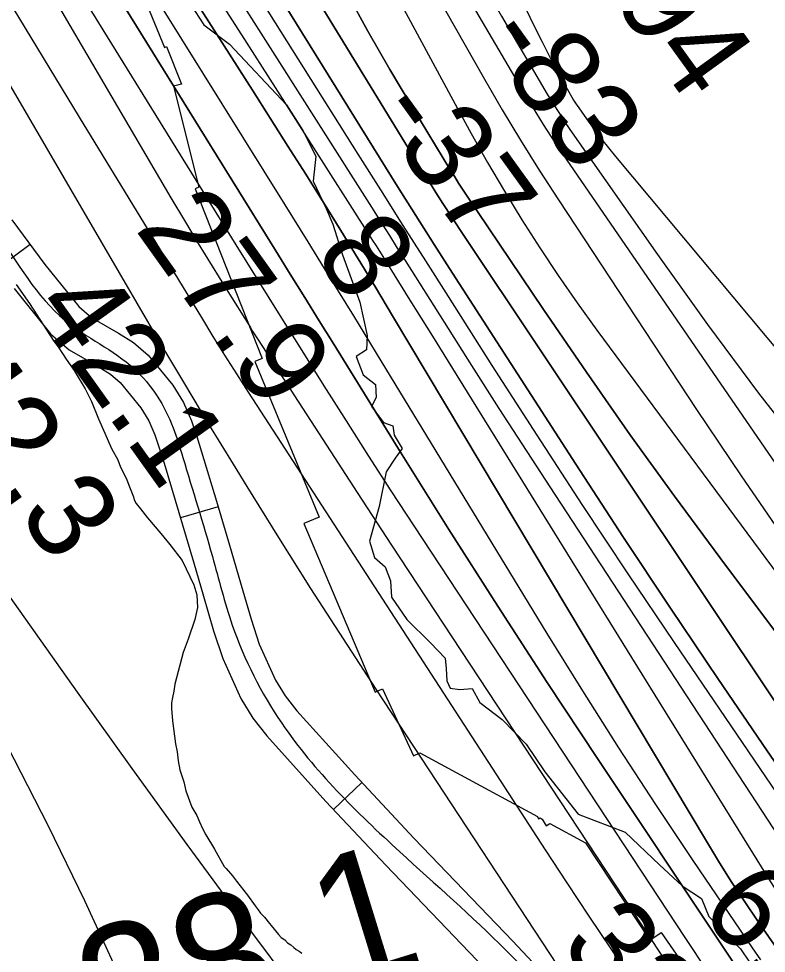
# Model space of a CAD drawing. Extents: x 3187622 to 3225504, y 800805 to 826213.
# Drawn here: x 3198341 to 3198914, y 817453 to 818168 of the extents above; entities that cross this region are included whole.
import ezdxf

# ---------------------------------------------------------------- set-up
doc = ezdxf.new("R2010")
doc.units = 0
for name, color, linetype in [('V-RIVR-EDGE', 7, 'Continuous'), ('V-RIVR-RANG', 7, 'Continuous'), ('V-ROAD-CNTR', 7, 'Continuous'), ('V-RRAP-RVMT', 7, 'Continuous'), ('V-SITE-VEGE', 7, 'Continuous'), ('V-SURV-IDEN', 7, 'Continuous'), ('V-TOPO-DPTH', 7, 'Continuous'), ('V-TOPO-MAJR', 7, 'Continuous'), ('V-TOPO-MINR', 7, 'Continuous'), ('V-TOPO-WATR', 7, 'Continuous')]:
    doc.layers.add(name, color=color, linetype=linetype)

msp = doc.modelspace()

# ---------------------------------------------------------------- linework, layer by layer
at = {"layer": 'V-RIVR-EDGE'}
msp.add_lwpolyline([(3198462.96, 818194.58), (3198482.88, 818163.67), (3198502.41, 818148.84), (3198546.19, 818102.22), (3198558.75, 818082.63), (3198568.7, 818063.05), (3198566.48, 818043.93), (3198576.43, 818023.04), (3198581.61, 818010.85), (3198588.94, 817987.36), (3198602.33, 817951.25), (3198607.92, 817925.59), (3198607.46, 817914.72), (3198599.62, 817909.53), (3198604.8, 817895.61), (3198614.35, 817888.19), (3198614.76, 817878.19), (3198611.26, 817871.25), (3198620.36, 817859.05), (3198627.74, 817856.43), (3198628.59, 817849.47), (3198634.65, 817839.02), (3198629.42, 817831.65), (3198622.44, 817821.23), (3198617.16, 817794.73), (3198609.7, 817768.23), (3198613.58, 817755.62), (3198621.82, 817748.64), (3198625.71, 817737.77), (3198626.55, 817725.16), (3198638.24, 817708.18), (3198656.45, 817690.31), (3198667.73, 817678.54), (3198668.58, 817670.72), (3198668.99, 817661.15), (3198671.58, 817655.5), (3198678.97, 817654.61), (3198688.53, 817655.46), (3198694.16, 817644.57), (3198711.51, 817631.49), (3198729.72, 817612.75), (3198744.01, 817591.42), (3198769.58, 817559.19), (3198805.63, 817545.19), (3198832.08, 817520.35), (3198849.43, 817504.22), (3198864.18, 817494.62), (3198869.8, 817480.7), (3198894.08, 817455.86), (3198901.01, 817445.85)], dxfattribs=at)
at = {"layer": 'V-ROAD-CNTR'}
for p, q in [((3198349.62, 817995.47), (3198325.52, 817977.61)), ((3198493.66, 817794.53), (3198464.91, 817785.96)), ((3198603.98, 817583.25), (3198582.07, 817562.75))]:
    msp.add_line(p, q, dxfattribs=at)
for points in [[(3198335.71, 818014.25), (3198361.06, 817980.02), (3198387.04, 817947.98), (3198397.07, 817939.27), (3198417.36, 817927.58), (3198429, 817920.3), (3198440.14, 817910.71), (3198459.12, 817887.67), (3198467.28, 817874.28), (3198473.37, 817860.33), (3198477.43, 817848.28), (3198481.06, 817836.69), (3198492.42, 817798.7), (3198503.73, 817760.74), (3198511.39, 817734.39), (3198518.94, 817708.35), (3198525.28, 817689.25), (3198537.72, 817661.79), (3198545.14, 817649.77), (3198554.02, 817638.31), (3198598.47, 817589.15), (3198643.9, 817540.57), (3198719.63, 817461.94), (3198795.23, 817381.27)], [(3198337.34, 817961.64), (3198365.39, 817927.05), (3198379.59, 817914.72), (3198401.92, 817901.86), (3198411.16, 817896.07), (3198418.62, 817889.65), (3198434.62, 817870.24), (3198440.6, 817860.41), (3198445.36, 817849.52), (3198448.9, 817839.01), (3198452.37, 817827.91), (3198463.67, 817790.12), (3198474.95, 817752.27), (3198482.58, 817726.03), (3198490.29, 817699.45), (3198497.3, 817678.3), (3198511.19, 817647.66), (3198520.45, 817632.65), (3198531.01, 817619.03), (3198576.38, 817568.84), (3198622.14, 817519.92), (3198697.88, 817441.28)]]:
    msp.add_lwpolyline(points, dxfattribs=at)
msp.add_spline([(3197108.01, 817982.2), (3197162.34, 817991.13), (3197229.38, 818001.88), (3197259.08, 817993.64), (3197361.14, 818001.17), (3197493.79, 818058.56), (3197592.21, 818133.8), (3197727.97, 818194.32), (3197773.22, 818262.2), (3197795.85, 818360.06), (3197841.1, 818435.29), (3197893.71, 818488.46), (3197938.96, 818518.44), (3197968.94, 818533.71), (3198014.19, 818525.8), (3198044.74, 818495.82), (3198127.32, 818420.58), (3198203.12, 818307.45), (3198233.1, 818209.03), (3198255.73, 818133.8), (3198278.35, 818073.27), (3198323.61, 818005.39), (3198376.21, 817937.52), (3198429.38, 817900.18), (3198459.36, 817854.93), (3198466.72, 817832.3), (3198489.34, 817756.51), (3198504.61, 817703.9), (3198542.51, 817628.67), (3198633.02, 817530.24), (3198783.48, 817371.86), (3198859.28, 817221.4), (3198934.51, 817108.26)], degree=3, dxfattribs=at)
at = {"layer": 'V-RRAP-RVMT'}
for p, q in [((3198437.21, 818183.77), (3198452.62, 818146.32)), ((3198452.62, 818146.32), (3198454.19, 818146.91)), ((3198454.19, 818146.91), (3198465.79, 818118.21)), ((3198465.79, 818118.21), (3198459.46, 818116.68)), ((3198459.46, 818116.68), (3198479.05, 818039.2)), ((3198479.05, 818039.2), (3198476.17, 818038.11)), ((3198476.17, 818038.11), (3198527.37, 817908.12)), ((3198527.37, 817908.12), (3198521.83, 817905.82)), ((3198521.83, 817905.82), (3198571.13, 817786.62)), ((3198571.13, 817786.62), (3198559.38, 817781.75)), ((3198559.38, 817781.75), (3198614.13, 817652.53)), ((3198614.13, 817652.53), (3198619.8, 817654.96)), ((3198619.8, 817654.96), (3198643.49, 817603.67)), ((3198643.49, 817603.67), (3198648.37, 817606.06)), ((3198648.37, 817606.06), (3198738.42, 817557.21)), ((3198738.42, 817557.21), (3198739.13, 817555.62)), ((3198739.13, 817555.62), (3198740.4, 817556.17)), ((3198740.4, 817556.17), (3198742.03, 817555.29)), ((3198742.03, 817555.29), (3198745.19, 817550.29)), ((3198745.19, 817550.29), (3198747.97, 817552.07)), ((3198747.97, 817552.07), (3198775.21, 817537.26)), ((3198775.21, 817537.26), (3198824.67, 817462.67)), ((3198824.67, 817462.67), (3198833.25, 817468.42)), ((3198833.25, 817468.42), (3198856.19, 817435.63))]:
    msp.add_line(p, q, dxfattribs=at)
at = {"layer": 'V-SITE-VEGE'}
for p, q in [((3198338.85, 817964.69), (3198349.09, 817950.23)), ((3198349.09, 817950.23), (3198367.96, 817921.3)), ((3198367.96, 817921.3), (3198371.23, 817916.89)), ((3198371.23, 817916.89), (3198377.39, 817907.65)), ((3198377.39, 817907.65), (3198383.53, 817898.82)), ((3198383.53, 817898.82), (3198391.75, 817884.74)), ((3198391.75, 817884.74), (3198396.69, 817875.08)), ((3198396.69, 817875.08), (3198402.07, 817861.8)), ((3198402.07, 817861.8), (3198407.03, 817850.93)), ((3198407.03, 817850.93), (3198411.99, 817839.25)), ((3198411.99, 817839.25), (3198416.93, 817830.4)), ((3198416.93, 817830.4), (3198419, 817824.76)), ((3198419, 817824.76), (3198423.53, 817815.91)), ((3198423.53, 817815.91), (3198425.19, 817811.08)), ((3198425.19, 817811.08), (3198428.92, 817802.22)), ((3198428.92, 817802.22), (3198429.34, 817799.8)), ((3198429.34, 817799.8), (3198430.99, 817796.98)), ((3198430.99, 817796.98), (3198434.26, 817792.97)), ((3198434.26, 817792.97), (3198439.58, 817786.15)), ((3198439.58, 817786.15), (3198449.8, 817774.12)), ((3198449.8, 817774.12), (3198456.75, 817765.69)), ((3198456.75, 817765.69), (3198466.17, 817753.25)), ((3198466.17, 817753.25), (3198475.23, 817734.74)), ((3198475.23, 817734.74), (3198477.33, 817727.08)), ((3198477.33, 817727.08), (3198477.82, 817717.38)), ((3198477.82, 817717.38), (3198475.89, 817708.07)), ((3198475.89, 817708.07), (3198470.78, 817693.06)), ((3198470.78, 817693.06), (3198466.83, 817682.92)), ((3198466.83, 817682.92), (3198460.59, 817658.6)), ((3198459.83, 817653.34), (3198458.67, 817648.48)), ((3198460.59, 817658.6), (3198459.83, 817653.34)), ((3198458.67, 817648.48), (3198457.9, 817644.43)), ((3198457.9, 817644.43), (3198457.94, 817639.98)), ((3198457.94, 817639.98), (3198458.83, 817630.69)), ((3198458.83, 817630.69), (3198461.02, 817612.92)), ((3198461.02, 817612.92), (3198462.29, 817606.87)), ((3198462.29, 817606.87), (3198463.17, 817600.01)), ((3198463.17, 817600.01), (3198464.44, 817593.15)), ((3198464.44, 817593.15), (3198467.36, 817583.88)), ((3198467.36, 817583.88), (3198469.04, 817577.02)), ((3198469.04, 817577.02), (3198473.61, 817564.53)), ((3198473.61, 817564.53), (3198477.31, 817558.1)), ((3198477.31, 817558.1), (3198479.38, 817553.27)), ((3198479.38, 817553.27), (3198481.85, 817548.04)), ((3198481.85, 817548.04), (3198484.32, 817543.21)), ((3198484.32, 817543.21), (3198490.89, 817532.36)), ((3198490.89, 817532.36), (3198498.29, 817519.08)), ((3198498.29, 817519.08), (3198499.93, 817517.48)), ((3198499.93, 817517.48), (3198504.83, 817511.87)), ((3198504.83, 817511.87), (3198507.7, 817507.86)), ((3198507.7, 817507.86), (3198516.29, 817497.02)), ((3198516.29, 817497.02), (3198522.02, 817488.99)), ((3198522.02, 817488.99), (3198524.48, 817485.78)), ((3198524.48, 817485.78), (3198526.12, 817483.37)), ((3198526.12, 817483.37), (3198529.39, 817480.17)), ((3198529.39, 817480.17), (3198533.07, 817475.35)), ((3198533.07, 817475.35), (3198534.3, 817473.74)), ((3198534.3, 817473.74), (3198540.02, 817466.93)), ((3198540.02, 817466.93), (3198542.06, 817464.52)), ((3198542.06, 817464.52), (3198544.91, 817462.93)), ((3198544.91, 817462.93), (3198546.95, 817460.52)), ((3198546.95, 817460.52), (3198549.39, 817458.93)), ((3198549.39, 817458.93), (3198551.84, 817456.93)), ((3198551.84, 817456.93), (3198553.47, 817455.33)), ((3198553.47, 817455.33), (3198555.91, 817454.14)), ((3198555.91, 817454.14), (3198557.95, 817452.54))]:
    msp.add_line(p, q, dxfattribs=at)
at = {"layer": 'V-TOPO-DPTH'}
for points in [[(3198152.22, 818754.17), (3198256.7, 818585.99), (3198313.23, 818495.3), (3198369.94, 818404.72), (3198426.92, 818314.32), (3198484.09, 818224.03), (3198612.93, 818021.23), (3198618.97, 818011.71), (3198625, 818002.2), (3198631.02, 817992.67), (3198637.03, 817983.15), (3198666.84, 817935.85), (3198687.84, 817902.72), (3198708.96, 817869.67), (3198730.25, 817836.73), (3198751.65, 817803.86), (3198932.33, 817527.96), (3198948.71, 817503.46), (3198965.4, 817479.17), (3198982.55, 817455.21), (3199000.01, 817431.46)], [(3198152.22, 818754.17), (3198256.7, 818585.99), (3198313.23, 818495.3), (3198369.94, 818404.72), (3198426.92, 818314.32), (3198484.09, 818224.03), (3198612.93, 818021.23), (3198618.97, 818011.71), (3198625, 818002.2), (3198631.02, 817992.67), (3198637.03, 817983.15), (3198666.84, 817935.85), (3198687.84, 817902.72), (3198708.96, 817869.67), (3198730.25, 817836.73), (3198751.65, 817803.86), (3198932.33, 817527.96), (3198948.71, 817503.46), (3198965.4, 817479.17), (3198982.55, 817455.21), (3199000.01, 817431.46)], [(3198987.7, 817544.61), (3198679.53, 818006.19), (3198671.32, 818018.65), (3198663.2, 818031.18), (3198655.24, 818043.8), (3198647.38, 818056.48), (3198566.36, 818188.91), (3198518.5, 818268.12), (3198471.22, 818347.66), (3198424.8, 818427.72), (3198378.97, 818508.11), (3198244.61, 818746.78)], [(3198244.61, 818746.78), (3198378.97, 818508.11), (3198424.8, 818427.72), (3198471.22, 818347.66), (3198518.5, 818268.12), (3198566.36, 818188.91), (3198647.38, 818056.48), (3198655.24, 818043.8), (3198663.2, 818031.18), (3198671.32, 818018.65), (3198679.53, 818006.19), (3198987.7, 817544.61)], [(3198925.67, 817450.87), (3198923.65, 817453.73), (3198907.29, 817477.27), (3198897.26, 817492.01), (3198887.44, 817506.88), (3198877.94, 817521.95), (3198868.64, 817537.16), (3198627.43, 817940.81), (3198614.32, 817962.59), (3198601.12, 817984.33), (3198587.78, 818005.98), (3198574.36, 818027.57), (3198560.84, 818049.11), (3198547.28, 818070.62), (3198533.65, 818092.09), (3198519.99, 818113.54), (3198140.09, 818707.79)], [(3198140.09, 818707.79), (3198519.99, 818113.54), (3198533.65, 818092.09), (3198547.28, 818070.62), (3198560.84, 818049.11), (3198574.36, 818027.57), (3198587.78, 818005.98), (3198601.12, 817984.33), (3198614.32, 817962.59), (3198627.43, 817940.81), (3198868.64, 817537.16), (3198877.94, 817521.95), (3198887.44, 817506.88), (3198897.26, 817492.01), (3198907.29, 817477.27), (3198923.65, 817453.73), (3198925.67, 817450.87)], [(3199249.34, 817166.94), (3199005.9, 817477.94), (3198997.72, 817488.6), (3198989.66, 817499.34), (3198981.8, 817510.23), (3198974.07, 817521.22), (3198914.39, 817607.66), (3198877.17, 817662.11), (3198840.29, 817716.78), (3198803.92, 817771.8), (3198767.9, 817827.05), (3198673.42, 817973.41), (3198659.28, 817995.44), (3198645.22, 818017.52), (3198631.27, 818039.68), (3198617.4, 818061.88), (3198320.09, 818540.42), (3198295.32, 818580.49), (3198270.68, 818620.65), (3198246.22, 818660.91), (3198221.89, 818701.26)], [(3198221.89, 818701.26), (3198246.22, 818660.91), (3198270.68, 818620.65), (3198295.32, 818580.49), (3198320.09, 818540.42), (3198617.4, 818061.88), (3198631.27, 818039.68), (3198645.22, 818017.52), (3198659.28, 817995.44), (3198673.42, 817973.41), (3198767.9, 817827.05), (3198803.92, 817771.8), (3198840.29, 817716.78), (3198877.17, 817662.11), (3198914.39, 817607.66), (3198974.07, 817521.22), (3198981.8, 817510.23), (3198989.66, 817499.34), (3198997.72, 817488.6), (3199005.9, 817477.94), (3199249.34, 817166.94)], [(3198890.07, 817443.38), (3198878.59, 817460.42), (3198784.36, 817601.69), (3198745.96, 817659.89), (3198707.96, 817718.35), (3198670.55, 817777.18), (3198633.53, 817836.27), (3198582.29, 817918.99), (3198571.19, 817936.91), (3198560.09, 817954.82), (3198548.98, 817972.73), (3198537.86, 817990.64), (3198175.24, 818574.89), (3198158.91, 818601.16), (3198142.54, 818627.4), (3198126.13, 818653.62), (3198109.68, 818679.82)], [(3199002.45, 817590.04), (3198878.11, 817755.74), (3198843.49, 817802.62), (3198809.35, 817849.85), (3198775.95, 817897.59), (3198743.03, 817945.68), (3198684.1, 818033.21), (3198681.04, 818037.81), (3198678.02, 818042.45), (3198675.07, 818047.12), (3198672.16, 818051.82), (3198642.62, 818100.22), (3198625.31, 818129.33), (3198608.45, 818158.7), (3198592.29, 818188.44), (3198576.57, 818218.45), (3198536.12, 818297.92), (3198500.47, 818367.83), (3198464.76, 818437.7), (3198428.95, 818507.52), (3198393.07, 818577.31), (3198346.96, 818666.85)], [(3198346.96, 818666.85), (3198393.07, 818577.31), (3198428.95, 818507.52), (3198464.76, 818437.7), (3198500.47, 818367.83), (3198536.12, 818297.92), (3198576.57, 818218.45), (3198592.29, 818188.44), (3198608.45, 818158.7), (3198625.31, 818129.33), (3198642.62, 818100.22), (3198672.16, 818051.82), (3198675.07, 818047.12), (3198678.02, 818042.45), (3198681.04, 818037.81), (3198684.1, 818033.21), (3198743.03, 817945.68), (3198775.95, 817897.59), (3198809.35, 817849.85), (3198843.49, 817802.62), (3198878.11, 817755.74), (3199002.45, 817590.04)]]:
    msp.add_lwpolyline(points, dxfattribs=at)
at = {"layer": 'V-TOPO-MAJR'}
for points in [[(3198342.95, 818716.99), (3198374.42, 818659.39), (3198405.82, 818601.75), (3198437.12, 818544.05), (3198468.34, 818486.32), (3198675.34, 818102.78), (3198687.67, 818080.41), (3198700.27, 818058.2), (3198713.26, 818036.21), (3198726.51, 818014.37), (3198740.23, 817992.83), (3198754.3, 817971.53), (3198768.89, 817950.58), (3198783.84, 817929.87), (3199038.64, 817585.91), (3199049.32, 817571.77), (3199060.18, 817557.77), (3199071.3, 817543.98), (3199082.59, 817530.32), (3199213.51, 817375.02), (3199266.5, 817312.77), (3199319.89, 817250.88), (3199373.89, 817189.52)], [(3198051.2, 818669.08), (3198170.24, 818460.43), (3198223.54, 818367.96), (3198277.39, 818275.8), (3198332.05, 818184.13), (3198387.25, 818092.77), (3198480.89, 817939.34), (3198489.73, 817924.98), (3198498.66, 817910.67), (3198507.71, 817896.43), (3198516.84, 817882.25), (3198744.39, 817531.87), (3198761.04, 817506.43), (3198777.81, 817481.08), (3198794.77, 817455.84), (3198811.85, 817430.69)]]:
    msp.add_lwpolyline(points, dxfattribs=at)
at = {"layer": 'V-TOPO-MINR'}
for points in [[(3198322.86, 818793.33), (3198394.83, 818662), (3198443.95, 818572.84), (3198493.33, 818483.83), (3198543.13, 818395.04), (3198593.19, 818306.4), (3198697.9, 818121.96), (3198711.51, 818098.54), (3198725.43, 818075.3), (3198739.8, 818052.35), (3198754.48, 818029.58), (3198860.3, 817869.04), (3198894.51, 817818.1), (3198929.31, 817767.57), (3198964.97, 817717.65), (3199001.22, 817668.13), (3199064.91, 817582.69), (3199069.8, 817576.25), (3199074.78, 817569.88), (3199079.87, 817563.6), (3199085.05, 817557.38), (3199131.67, 817502.48), (3199160.38, 817469.02), (3199189.33, 817435.75)], [(3198349.13, 818785.06), (3198502.32, 818505.68), (3198541.3, 818435.29), (3198580.69, 818365.14), (3198620.67, 818295.32), (3198661.05, 818225.73), (3198725.88, 818115.13), (3198734.3, 818101.11), (3198742.92, 818087.21), (3198751.85, 818073.51), (3198760.97, 818059.94), (3199041.41, 817652.3), (3199049.56, 817640.74), (3199057.88, 817629.32), (3199066.46, 817618.09), (3199075.22, 817606.98), (3199084.24, 817596.09), (3199093.43, 817585.36), (3199102.89, 817574.85), (3199112.52, 817564.5), (3199476.76, 817182.58)], [(3198152.22, 818754.17), (3198256.7, 818585.99), (3198313.23, 818495.3), (3198369.94, 818404.72), (3198426.92, 818314.32), (3198484.09, 818224.03), (3198612.93, 818021.23), (3198618.97, 818011.71), (3198625, 818002.2), (3198631.02, 817992.67), (3198637.03, 817983.15), (3198666.84, 817935.85), (3198687.84, 817902.72), (3198708.96, 817869.67), (3198730.25, 817836.73), (3198751.65, 817803.86), (3198932.33, 817527.96), (3198948.71, 817503.46), (3198965.4, 817479.17), (3198982.55, 817455.21), (3199000.01, 817431.46)], [(3198244.61, 818746.78), (3198378.97, 818508.11), (3198424.8, 818427.72), (3198471.22, 818347.66), (3198518.5, 818268.12), (3198566.36, 818188.91), (3198647.38, 818056.48), (3198655.24, 818043.8), (3198663.2, 818031.18), (3198671.32, 818018.65), (3198679.53, 818006.19), (3198987.7, 817544.61)], [(3198146.49, 818732.38), (3198460.28, 818236.76), (3198485.93, 818196.31), (3198511.61, 818155.88), (3198537.36, 818115.49), (3198563.14, 818075.12), (3198609.55, 818002.54), (3198612.15, 817998.47), (3198614.73, 817994.4), (3198617.3, 817990.32), (3198619.86, 817986.23), (3198632.07, 817966.7), (3198640.72, 817952.83), (3198649.36, 817938.96), (3198657.99, 817925.08), (3198666.61, 817911.2), (3198913.25, 817513.32), (3198929.31, 817487.96), (3198945.7, 817462.82), (3198962.58, 817438)], [(3198466.98, 818733.21), (3198505.3, 818656.53), (3198542.98, 818579.54), (3198579.71, 818502.08), (3198615.8, 818424.32), (3198717.54, 818201.49), (3198723.5, 818188.64), (3198729.56, 818175.85), (3198735.78, 818163.13), (3198742.11, 818150.46), (3198749.32, 818136.22), (3198752.17, 818130.74), (3198755.08, 818125.29), (3198758.09, 818119.89), (3198761.16, 818114.53), (3198766.15, 818106.03), (3198768.15, 818102.86), (3198768.87, 818101.82), (3198777.35, 818089.86), (3198782.39, 818082.92), (3198787.55, 818076.07), (3198792.87, 818069.34), (3198798.3, 818062.69), (3199147.53, 817645.35)], [(3198066.75, 818719.59), (3198161.12, 818561.11), (3198210.21, 818479.12), (3198259.59, 818397.31), (3198309.38, 818315.74), (3198359.45, 818234.35), (3198507.41, 817995.17), (3198524.18, 817968.12), (3198540.98, 817941.09), (3198557.84, 817914.09), (3198574.73, 817887.11), (3198591.73, 817860.21), (3198608.86, 817833.38), (3198626.16, 817806.67), (3198643.59, 817780.03), (3198851.41, 817464.63), (3198868.53, 817438.89)], [(3198419.45, 818715.85), (3198626.69, 818321.97), (3198647.16, 818283.7), (3198667.98, 818245.63), (3198689.32, 818207.85), (3198711.01, 818170.26), (3198746.01, 818110.58), (3198750.55, 818103.04), (3198755.22, 818095.57), (3198760.06, 818088.22), (3198765.02, 818080.95), (3198830.36, 817987.6), (3198868.72, 817934.2), (3198907.92, 817881.44), (3198948.4, 817829.65), (3198989.73, 817778.51), (3199096.02, 817650.22), (3199111.57, 817631.74), (3199127.31, 817613.43), (3199143.34, 817595.36), (3199159.55, 817577.46), (3199252.09, 817476.87), (3199312.31, 817411.03), (3199372.27, 817344.96)], [(3198062.25, 818704.66), (3198457.57, 818031.14), (3198467.95, 818013.63), (3198478.42, 817996.18), (3198489.05, 817978.82), (3198499.77, 817961.52), (3198518.43, 817931.69), (3198519.9, 817929.35), (3198521.38, 817927.01), (3198522.88, 817924.68), (3198524.38, 817922.35), (3198573.97, 817846.01), (3198600.32, 817805.54), (3198626.71, 817765.1), (3198653.19, 817724.72), (3198679.72, 817684.37), (3198852.66, 817421.96)], [(3198221.89, 818701.26), (3198246.22, 818660.91), (3198270.68, 818620.65), (3198295.32, 818580.49), (3198320.09, 818540.42), (3198617.4, 818061.88), (3198631.27, 818039.68), (3198645.22, 818017.52), (3198659.28, 817995.44), (3198673.42, 817973.41), (3198767.9, 817827.05), (3198803.92, 817771.8), (3198840.29, 817716.78), (3198877.17, 817662.11), (3198914.39, 817607.66), (3198974.07, 817521.22), (3198981.8, 817510.23), (3198989.66, 817499.34), (3198997.72, 817488.6), (3199005.9, 817477.94), (3199249.34, 817166.94)], [(3198109.68, 818679.82), (3198126.13, 818653.62), (3198142.54, 818627.4), (3198158.91, 818601.16), (3198175.24, 818574.89), (3198537.86, 817990.64), (3198548.98, 817972.73), (3198560.09, 817954.82), (3198571.19, 817936.91), (3198582.29, 817918.99), (3198633.53, 817836.27), (3198670.55, 817777.18), (3198707.96, 817718.35), (3198745.96, 817659.89), (3198784.36, 817601.69), (3198878.59, 817460.42), (3198890.07, 817443.38)], [(3198132.86, 818681.23), (3198213.39, 818554.16), (3198272.67, 818460.38), (3198331.82, 818366.51), (3198390.76, 818272.52), (3198449.57, 818178.44), (3198544.75, 818025.8), (3198562.36, 817997.46), (3198579.91, 817969.08), (3198597.38, 817940.65), (3198614.79, 817912.18), (3198745.63, 817697.5), (3198772.87, 817653.55), (3198800.52, 817609.87), (3198828.82, 817566.6), (3198857.54, 817523.61), (3198902.94, 817456.73), (3198909.33, 817447.42)], [(3198214.61, 818677.59), (3198226.59, 818658.48), (3198600.84, 818064.65), (3198618.08, 818037.34), (3198635.34, 818010.04), (3198652.64, 817982.76), (3198669.96, 817955.5), (3198703.5, 817902.8), (3198737.84, 817849.36), (3198772.52, 817796.13), (3198807.68, 817743.23), (3198843.16, 817690.53), (3198956.53, 817523.83), (3198967.97, 817507.34), (3198979.61, 817491), (3198991.55, 817474.87), (3199003.69, 817458.89), (3199374.89, 816979.49)], [(3198346.96, 818666.85), (3198393.07, 818577.31), (3198428.95, 818507.52), (3198464.76, 818437.7), (3198500.47, 818367.83), (3198536.12, 818297.92), (3198576.57, 818218.45), (3198592.29, 818188.44), (3198608.45, 818158.7), (3198625.31, 818129.33), (3198642.62, 818100.22), (3198672.16, 818051.82), (3198675.07, 818047.12), (3198678.02, 818042.45), (3198681.04, 818037.81), (3198684.1, 818033.21), (3198743.03, 817945.68), (3198775.95, 817897.59), (3198809.35, 817849.85), (3198843.49, 817802.62), (3198878.11, 817755.74), (3199002.45, 817590.04)], [(3198020.05, 818661.79), (3198038.46, 818628.67), (3198052.11, 818604.36), (3198077.6, 818559.22), (3198103.24, 818514.16), (3198129.1, 818469.23), (3198155.09, 818424.38), (3198431.36, 817950.37), (3198449.56, 817919.41), (3198467.9, 817888.54), (3198486.48, 817857.8), (3198505.2, 817827.15), (3198515.79, 817809.96), (3198540.1, 817770.89), (3198564.63, 817731.98), (3198589.51, 817693.28), (3198614.63, 817654.73), (3198782.4, 817399.66)], [(3198316.81, 817749.42), (3198385.74, 817652.46), (3198427.64, 817594.02), (3198469.84, 817535.8), (3198512.51, 817477.93), (3198555.48, 817420.28)], [(3198418.11, 817435.06), (3198391.61, 817492.77), (3198363.63, 817549.84), (3198300.38, 817672.88)]]:
    msp.add_lwpolyline(points, dxfattribs=at)
at = {"layer": 'V-TOPO-WATR'}
msp.add_lwpolyline([(3198140.09, 818707.79), (3198519.99, 818113.54), (3198533.65, 818092.09), (3198547.28, 818070.62), (3198560.84, 818049.11), (3198574.36, 818027.57), (3198587.78, 818005.98), (3198601.12, 817984.33), (3198614.32, 817962.59), (3198627.43, 817940.81), (3198868.64, 817537.16), (3198877.94, 817521.95), (3198887.44, 817506.88), (3198897.26, 817492.01), (3198907.29, 817477.27), (3198923.65, 817453.73), (3198925.67, 817450.87)], dxfattribs=at)

# ---------------------------------------------------------------- texts
at = {"layer": 'V-RIVR-RANG'}
for s, rotation, p in [('-94', 305.83608, (3198777.83, 818207.32)), ('-83', 305.83608, (3198693.99, 818152.6)), ('-37', 305.83608, (3198611.55, 818095.96)), ('27.9', 305.55833, (3198429.42, 818007.52)), ('8', 305.83608, (3198566.16, 817988)), ('42.1', 305.55833, (3198349.75, 817947.03)), ('42.3', 305.55833, (3198267.16, 817890.61)), ('6.3', 309.76153, (3198861.22, 817486.38)), ('32.3', 309.49833, (3198754.67, 817458.94))]:
    msp.add_text(s, height=67, rotation=rotation, dxfattribs=at).set_placement(p)
at = {"layer": 'V-SURV-IDEN'}
msp.add_text('1418+38.1', height=100, rotation=17.12028, dxfattribs=at).set_placement((3198047.27, 817257.51))

doc.saveas('drawing.dxf')
